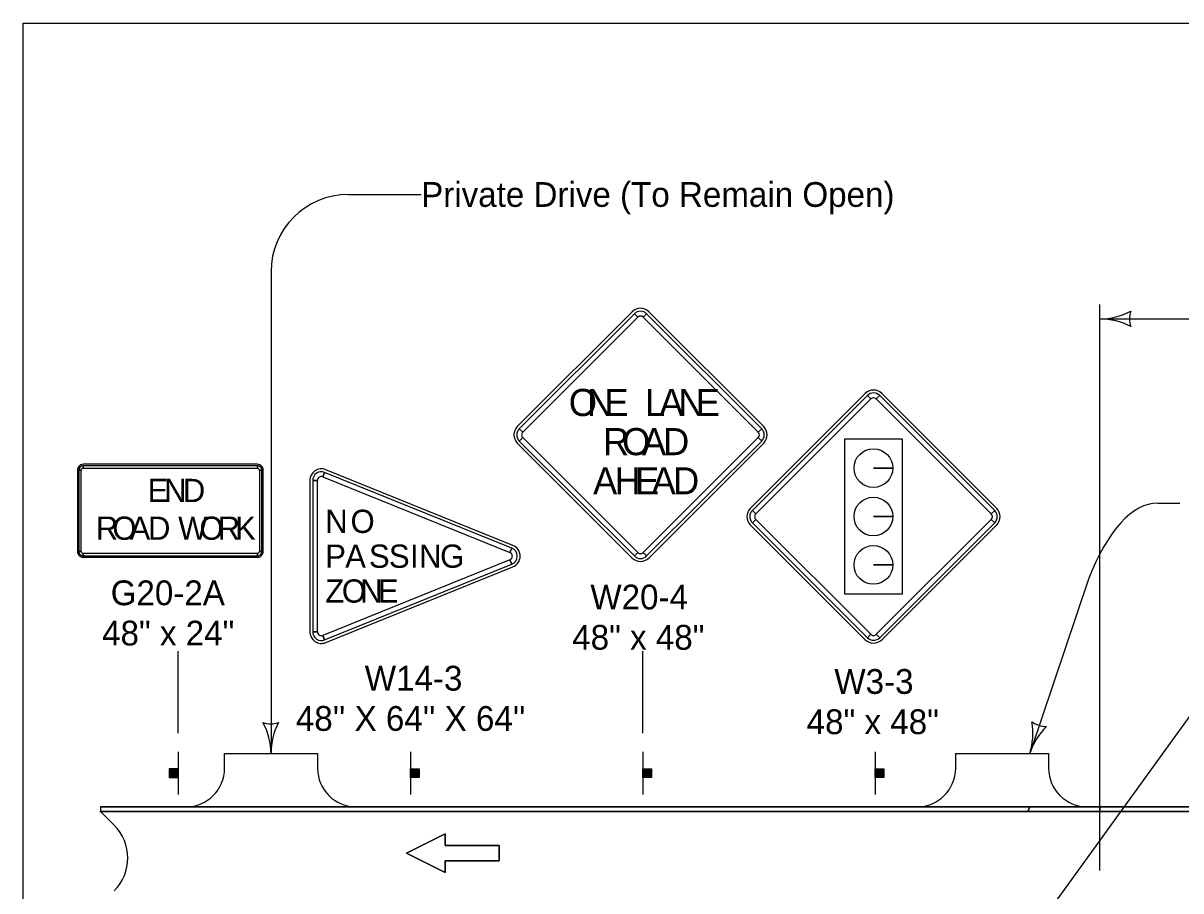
# Model space of a CAD drawing. Extents: x -2134934 to -2122394, y -2139046 to -2137036.
# Drawn here: x -2134934 to -2134187, y -2137596 to -2137036 of the extents above; entities that cross this region are included whole.
import ezdxf

# ---------------------------------------------------------------- set-up
doc = ezdxf.new("R2010")
doc.units = 0
for name, color, linetype in [('Barrier', 7, 'Continuous'), ('BridgeSuperStructureExisting', 7, 'Continuous'), ('Default', 7, 'Continuous'), ('DsnShtPlotIdentification', 7, 'Continuous'), ('DsnShtPlotShape', 7, 'Continuous')]:
    doc.layers.add(name, color=color, linetype=linetype)

msp = doc.modelspace()

# ---------------------------------------------------------------- linework, layer by layer
at = {"layer": 'Barrier'}
for p, q in [((-2134541.21, -2137222.31), (-2134615.45, -2137296.56)), ((-2134456.35, -2137296.56), (-2134530.6, -2137222.31)), ((-2134539.88, -2137223.64), (-2134537.67, -2137225.85)), ((-2134534.14, -2137225.85), (-2134531.93, -2137223.64)), ((-2134390.77, -2137275.12), (-2134465.02, -2137349.37)), ((-2134389.45, -2137276.45), (-2134387.24, -2137278.66)), ((-2134383.7, -2137278.66), (-2134381.49, -2137276.45)), ((-2134305.92, -2137349.37), (-2134380.17, -2137275.12)), ((-2134611.92, -2137300.09), (-2134614.13, -2137297.88)), ((-2134614.13, -2137305.84), (-2134611.92, -2137303.63)), ((-2134457.68, -2137297.88), (-2134459.89, -2137300.09)), ((-2134459.89, -2137303.63), (-2134457.68, -2137305.84)), ((-2134615.45, -2137307.16), (-2134541.21, -2137381.41)), ((-2134530.6, -2137381.41), (-2134456.35, -2137307.16)), ((-2134899.41, -2137324.64), (-2134899.41, -2137377.14)), ((-2134898.48, -2137324.64), (-2134896.91, -2137324.64)), ((-2134783.16, -2137320.89), (-2134895.66, -2137320.89)), ((-2134895.66, -2137323.39), (-2134895.66, -2137321.82)), ((-2134783.16, -2137321.82), (-2134783.16, -2137323.39)), ((-2134781.91, -2137324.64), (-2134780.35, -2137324.64)), ((-2134779.41, -2137377.14), (-2134779.41, -2137324.64)), ((-2134740.97, -2137329.01), (-2134739.8, -2137326.11)), ((-2134618.27, -2137373.25), (-2134739.1, -2137324.37)), ((-2134373.06, -2137323.34), (-2134385.56, -2137323.34)), ((-2134385.56, -2137323.34), (-2134373.06, -2137323.34)), ((-2134749.41, -2137331.32), (-2134749.41, -2137429.07)), ((-2134747.53, -2137331.32), (-2134744.41, -2137331.32)), ((-2134461.48, -2137352.9), (-2134463.69, -2137350.69)), ((-2134463.69, -2137358.65), (-2134461.48, -2137356.44)), ((-2134373.06, -2137354.59), (-2134385.56, -2137354.59)), ((-2134385.56, -2137354.59), (-2134373.06, -2137354.59)), ((-2134307.25, -2137350.69), (-2134309.45, -2137352.9)), ((-2134309.45, -2137356.44), (-2134307.25, -2137358.65)), ((-2134465.02, -2137359.98), (-2134390.77, -2137434.22)), ((-2134380.17, -2137434.22), (-2134305.92, -2137359.98)), ((-2134896.91, -2137377.14), (-2134898.48, -2137377.14)), ((-2134895.66, -2137379.95), (-2134895.66, -2137378.39)), ((-2134783.16, -2137378.39), (-2134783.16, -2137379.95)), ((-2134780.35, -2137377.14), (-2134781.91, -2137377.14)), ((-2134618.98, -2137374.98), (-2134620.15, -2137377.88)), ((-2134537.67, -2137377.87), (-2134539.88, -2137380.08)), ((-2134531.93, -2137380.08), (-2134534.14, -2137377.87)), ((-2134895.66, -2137380.89), (-2134783.16, -2137380.89)), ((-2134620.15, -2137382.52), (-2134618.98, -2137385.41)), ((-2134373.06, -2137385.84), (-2134385.56, -2137385.84)), ((-2134385.56, -2137385.84), (-2134373.06, -2137385.84)), ((-2134739.1, -2137436.03), (-2134618.27, -2137387.15)), ((-2134744.41, -2137429.07), (-2134747.53, -2137429.07)), ((-2134739.8, -2137434.29), (-2134740.97, -2137431.39)), ((-2134387.24, -2137430.69), (-2134389.45, -2137432.9)), ((-2134381.49, -2137432.9), (-2134383.7, -2137430.69))]:
    msp.add_line(p, q, dxfattribs=at)
for points in [[(-2134539.88, -2137223.64), (-2134614.13, -2137297.88), (-2134611.92, -2137300.09), (-2134537.67, -2137225.85), (-2134539.88, -2137223.64)], [(-2134457.68, -2137297.88), (-2134531.93, -2137223.64), (-2134534.14, -2137225.85), (-2134459.89, -2137300.09), (-2134457.68, -2137297.88)], [(-2134389.45, -2137276.45), (-2134463.69, -2137350.69), (-2134461.48, -2137352.9), (-2134387.24, -2137278.66), (-2134389.45, -2137276.45)], [(-2134307.25, -2137350.69), (-2134381.49, -2137276.45), (-2134383.7, -2137278.66), (-2134309.45, -2137352.9), (-2134307.25, -2137350.69)], [(-2134614.13, -2137305.84), (-2134539.88, -2137380.08), (-2134537.67, -2137377.87), (-2134611.92, -2137303.63), (-2134614.13, -2137305.84)], [(-2134531.93, -2137380.08), (-2134457.68, -2137305.84), (-2134459.89, -2137303.63), (-2134534.14, -2137377.87), (-2134531.93, -2137380.08)], [(-2134366.74, -2137304.73), (-2134404.2, -2137304.73), (-2134404.2, -2137404.62), (-2134366.74, -2137404.62), (-2134366.74, -2137304.73)], [(-2134898.48, -2137324.64), (-2134898.48, -2137377.14), (-2134896.91, -2137377.14), (-2134896.91, -2137324.64), (-2134898.48, -2137324.64)], [(-2134783.16, -2137321.82), (-2134895.66, -2137321.82), (-2134895.66, -2137323.39), (-2134783.16, -2137323.39), (-2134783.16, -2137321.82)], [(-2134780.35, -2137377.14), (-2134780.35, -2137324.64), (-2134781.91, -2137324.64), (-2134781.91, -2137377.14), (-2134780.35, -2137377.14)], [(-2134618.98, -2137374.98), (-2134739.8, -2137326.11), (-2134740.97, -2137329.01), (-2134620.15, -2137377.88), (-2134618.98, -2137374.98)], [(-2134747.53, -2137331.32), (-2134747.53, -2137429.07), (-2134744.41, -2137429.07), (-2134744.41, -2137331.32), (-2134747.53, -2137331.32)], [(-2134463.69, -2137358.65), (-2134389.45, -2137432.9), (-2134387.24, -2137430.69), (-2134461.48, -2137356.44), (-2134463.69, -2137358.65)], [(-2134381.49, -2137432.9), (-2134307.25, -2137358.65), (-2134309.45, -2137356.44), (-2134383.7, -2137430.69), (-2134381.49, -2137432.9)], [(-2134895.66, -2137379.95), (-2134783.16, -2137379.95), (-2134783.16, -2137378.39), (-2134895.66, -2137378.39), (-2134895.66, -2137379.95)], [(-2134739.8, -2137434.29), (-2134618.98, -2137385.41), (-2134620.15, -2137382.52), (-2134740.97, -2137431.39), (-2134739.8, -2137434.29)]]:
    msp.add_lwpolyline(points, close=True, dxfattribs=at)
for centre in [(-2134385.56, -2137323.34), (-2134385.56, -2137354.59), (-2134385.56, -2137385.84)]:
    msp.add_circle(centre, 12.5, dxfattribs=at)
for centre, radius, start, end in [((-2134535.9, -2137227.61), 7.5, 44.99999, 134.99974), ((-2134535.9, -2137227.61), 5.62, 44.99999, 134.99974), ((-2134535.9, -2137227.61), 2.5, 44.99999, 134.99974), ((-2134385.47, -2137280.43), 7.5, 44.99999, 134.99974), ((-2134385.47, -2137280.43), 5.62, 44.99999, 134.99974), ((-2134385.47, -2137280.43), 2.5, 44.99999, 134.99974), ((-2134610.15, -2137301.86), 7.5, 134.99974, 224.99995), ((-2134461.66, -2137301.86), 7.5, 315.00016, 44.9998), ((-2134610.15, -2137301.86), 5.62, 134.99974, 224.99995), ((-2134610.15, -2137301.86), 2.5, 134.99974, 224.99995), ((-2134461.66, -2137301.86), 2.5, 315.00016, 44.9998), ((-2134461.66, -2137301.86), 5.62, 315.00016, 44.9998), ((-2134895.66, -2137324.64), 3.75, 90.00021, 179.99985), ((-2134895.66, -2137324.64), 2.81, 90.00021, 179.99985), ((-2134895.66, -2137324.64), 1.25, 90.00021, 179.99985), ((-2134783.16, -2137324.64), 3.75, 0, 90.00021), ((-2134783.16, -2137324.64), 2.81, 0, 90.00021), ((-2134783.16, -2137324.64), 1.25, 0, 90.00021), ((-2134741.91, -2137331.32), 7.5, 67.97571, 179.99985), ((-2134741.91, -2137331.32), 5.62, 67.97571, 179.99985), ((-2134741.91, -2137331.32), 2.5, 67.97571, 179.99985), ((-2134459.72, -2137354.67), 7.5, 134.99974, 224.99995), ((-2134311.22, -2137354.67), 7.5, 315.00016, 44.9998), ((-2134459.72, -2137354.67), 5.62, 134.99974, 224.99995), ((-2134459.72, -2137354.67), 2.5, 134.99974, 224.99995), ((-2134311.22, -2137354.67), 2.5, 315.00016, 44.9998), ((-2134311.22, -2137354.67), 5.62, 315.00016, 44.9998), ((-2134895.66, -2137377.14), 3.75, 179.99985, 270.00006), ((-2134895.66, -2137377.14), 2.81, 179.99985, 270.00006), ((-2134895.66, -2137377.14), 1.25, 179.99985, 270.00006), ((-2134783.16, -2137377.14), 3.75, 270.00006, 0.00027), ((-2134783.16, -2137377.14), 2.81, 270.00006, 0.00027), ((-2134783.16, -2137377.14), 1.25, 270.00006, 0.00027), ((-2134621.09, -2137380.2), 2.5, 292.02456, 67.97541), ((-2134621.09, -2137380.2), 5.62, 292.02456, 67.97541), ((-2134621.09, -2137380.2), 7.5, 292.02456, 67.97598), ((-2134535.9, -2137376.11), 2.5, 224.99995, 315.00016), ((-2134535.9, -2137376.11), 7.5, 224.99995, 315.00016), ((-2134535.9, -2137376.11), 5.62, 224.99995, 315.00016), ((-2134741.91, -2137429.07), 7.5, 179.99985, 292.02456), ((-2134741.91, -2137429.07), 5.62, 179.99985, 292.02456), ((-2134741.91, -2137429.07), 2.5, 179.99985, 292.02456), ((-2134385.47, -2137428.92), 2.5, 224.99995, 315.00016), ((-2134385.47, -2137428.92), 7.5, 224.99995, 315.00016), ((-2134385.47, -2137428.92), 5.62, 224.99995, 315.00016)]:
    msp.add_arc(centre, radius, start, end, dxfattribs=at)
at = {"layer": 'BridgeSuperStructureExisting'}
for p, q in [((-2134724.38, -2137146.61), (-2134677.51, -2137146.61)), ((-2134774.38, -2137196.61), (-2134774.38, -2137507.67)), ((-2134239.44, -2137583.23), (-2134239.44, -2137217.69)), ((-2134239.44, -2137226.98), (-2133580.02, -2137226.98)), ((-2134202.01, -2137345.99), (-2134187.79, -2137345.99)), ((-2134246.74, -2137395.12), (-2134284.66, -2137507.67)), ((-2134834.44, -2137494.5), (-2134834.44, -2137441.62)), ((-2134534.44, -2137494.5), (-2134534.44, -2137441.62)), ((-2134351.45, -2137718.98), (-2134176.64, -2137477.16)), ((-2134834.44, -2137506.66), (-2134834.44, -2137534.16)), ((-2134684.44, -2137506.66), (-2134684.44, -2137534.16)), ((-2134534.44, -2137506.66), (-2134534.44, -2137534.16)), ((-2134384.44, -2137506.66), (-2134384.44, -2137534.16)), ((-2134839.77, -2137517.52), (-2134839.77, -2137523.11)), ((-2134839.45, -2137523.11), (-2134839.45, -2137517.52)), ((-2134839.22, -2137517.52), (-2134839.22, -2137523.11)), ((-2134838.9, -2137523.11), (-2134838.9, -2137517.52)), ((-2134838.68, -2137517.52), (-2134838.7, -2137523.11)), ((-2134838.27, -2137523.11), (-2134838.25, -2137517.52)), ((-2134838.04, -2137517.52), (-2134838.04, -2137523.11)), ((-2134837.61, -2137523.11), (-2134837.61, -2137517.52)), ((-2134837.24, -2137517.52), (-2134837.24, -2137523.11)), ((-2134836.92, -2137523.11), (-2134836.9, -2137517.52)), ((-2134836.69, -2137517.52), (-2134836.69, -2137523.11)), ((-2134836.43, -2137523.11), (-2134836.43, -2137517.52)), ((-2134836.09, -2137517.52), (-2134836.09, -2137523.11)), ((-2134835.89, -2137523.11), (-2134835.89, -2137517.52)), ((-2134835.66, -2137517.52), (-2134835.66, -2137523.11)), ((-2134835.4, -2137523.11), (-2134835.4, -2137517.52)), ((-2134835.14, -2137517.52), (-2134835.14, -2137523.11)), ((-2134834.85, -2137523.11), (-2134834.85, -2137517.52)), ((-2134684.03, -2137523.11), (-2134684.03, -2137517.52)), ((-2134683.75, -2137517.52), (-2134683.75, -2137523.11)), ((-2134683.48, -2137523.11), (-2134683.48, -2137517.52)), ((-2134683.22, -2137517.52), (-2134683.22, -2137523.11)), ((-2134683, -2137523.11), (-2134683, -2137517.52)), ((-2134682.79, -2137517.52), (-2134682.79, -2137523.11)), ((-2134682.45, -2137523.11), (-2134682.45, -2137517.52)), ((-2134682.19, -2137517.52), (-2134682.19, -2137523.11)), ((-2134681.97, -2137523.11), (-2134681.98, -2137517.52)), ((-2134681.65, -2137517.52), (-2134681.65, -2137523.11)), ((-2134681.27, -2137523.11), (-2134681.27, -2137517.52)), ((-2134680.84, -2137517.52), (-2134680.84, -2137523.11)), ((-2134680.62, -2137523.11), (-2134680.63, -2137517.52)), ((-2134680.2, -2137517.52), (-2134680.18, -2137523.11)), ((-2134679.98, -2137523.11), (-2134679.98, -2137517.52)), ((-2134679.66, -2137517.52), (-2134679.66, -2137523.11)), ((-2134679.43, -2137523.11), (-2134679.43, -2137517.52)), ((-2134679.12, -2137517.52), (-2134679.12, -2137523.11)), ((-2134534.03, -2137523.11), (-2134534.03, -2137517.52)), ((-2134533.75, -2137517.52), (-2134533.75, -2137523.11)), ((-2134533.48, -2137523.11), (-2134533.48, -2137517.52)), ((-2134533.22, -2137517.52), (-2134533.22, -2137523.11)), ((-2134533, -2137523.11), (-2134533, -2137517.52)), ((-2134532.79, -2137517.52), (-2134532.79, -2137523.11)), ((-2134532.45, -2137523.11), (-2134532.45, -2137517.52)), ((-2134532.19, -2137517.52), (-2134532.19, -2137523.11)), ((-2134531.97, -2137523.11), (-2134531.98, -2137517.52)), ((-2134531.65, -2137517.52), (-2134531.65, -2137523.11)), ((-2134531.27, -2137523.11), (-2134531.27, -2137517.52)), ((-2134530.84, -2137517.52), (-2134530.84, -2137523.11)), ((-2134530.62, -2137523.11), (-2134530.63, -2137517.52)), ((-2134530.2, -2137517.52), (-2134530.18, -2137523.11)), ((-2134529.98, -2137523.11), (-2134529.98, -2137517.52)), ((-2134529.66, -2137517.52), (-2134529.66, -2137523.11)), ((-2134529.43, -2137523.11), (-2134529.43, -2137517.52)), ((-2134529.12, -2137517.52), (-2134529.12, -2137523.11)), ((-2134384.03, -2137523.11), (-2134384.03, -2137517.52)), ((-2134383.75, -2137517.52), (-2134383.75, -2137523.11)), ((-2134383.48, -2137523.11), (-2134383.48, -2137517.52)), ((-2134383.22, -2137517.52), (-2134383.22, -2137523.11)), ((-2134383, -2137523.11), (-2134383, -2137517.52)), ((-2134382.79, -2137517.52), (-2134382.79, -2137523.11)), ((-2134382.45, -2137523.11), (-2134382.45, -2137517.52)), ((-2134382.19, -2137517.52), (-2134382.19, -2137523.11)), ((-2134381.97, -2137523.11), (-2134381.98, -2137517.52)), ((-2134381.65, -2137517.52), (-2134381.65, -2137523.11)), ((-2134381.27, -2137523.11), (-2134381.27, -2137517.52)), ((-2134380.84, -2137517.52), (-2134380.84, -2137523.11)), ((-2134380.62, -2137523.11), (-2134380.63, -2137517.52)), ((-2134380.2, -2137517.52), (-2134380.18, -2137523.11)), ((-2134379.98, -2137523.11), (-2134379.98, -2137517.52)), ((-2134379.66, -2137517.52), (-2134379.66, -2137523.11)), ((-2134379.43, -2137523.11), (-2134379.43, -2137517.52)), ((-2134379.12, -2137517.52), (-2134379.12, -2137523.11)), ((-2134719.38, -2137542.16), (-2134829.38, -2137542.16)), ((-2134247.44, -2137542.16), (-2134357.44, -2137542.16)), ((-2134875.66, -2137553.94), (-2134884.44, -2137545.16)), ((-2133574.44, -2137545.16), (-2134884.44, -2137545.16)), ((-2134884.44, -2137545.16), (-2134875.65, -2137553.95))]:
    msp.add_line(p, q, dxfattribs=at)
for points in [[(-2134804.38, -2137517.16), (-2134804.38, -2137507.67), (-2134744.38, -2137507.67), (-2134744.38, -2137517.16)], [(-2134332.44, -2137517.16), (-2134332.44, -2137507.67), (-2134272.44, -2137507.67), (-2134272.44, -2137517.16)], [(-2134662.04, -2137577), (-2134662.04, -2137584.5), (-2134687.04, -2137572), (-2134662.04, -2137559.5), (-2134662.04, -2137567), (-2134627.04, -2137567), (-2134627.04, -2137577), (-2134662.04, -2137577)]]:
    msp.add_lwpolyline(points, dxfattribs=at)
for points in [[(-2134834.54, -2137523.11), (-2134834.54, -2137517.48), (-2134840.16, -2137517.48), (-2134840.16, -2137523.11)], [(-2134684.35, -2137523.11), (-2134684.35, -2137517.48), (-2134678.72, -2137517.48), (-2134678.72, -2137523.11)], [(-2134534.35, -2137523.11), (-2134534.35, -2137517.48), (-2134528.72, -2137517.48), (-2134528.72, -2137523.11)], [(-2134384.35, -2137523.11), (-2134384.35, -2137517.48), (-2134378.72, -2137517.48), (-2134378.72, -2137523.11)], [(-2134627.04, -2137577), (-2134627.04, -2137567), (-2134662.04, -2137567), (-2134662.04, -2137559.5), (-2134687.04, -2137572), (-2134662.04, -2137584.5), (-2134662.04, -2137577)]]:
    msp.add_lwpolyline(points, close=True, dxfattribs=at)
for centre, radius, start, end in [((-2134724.38, -2137196.61), 50, 90, 180), ((-2134829.38, -2137517.16), 25, 270, 0), ((-2134719.38, -2137517.16), 25, 180, 270), ((-2134357.44, -2137517.16), 25, 270, 360), ((-2134247.44, -2137517.16), 25, 180, 270), ((-2134896.87, -2137575.16), 30, 315, 45), ((-2134896.87, -2137575.16), 30, 315, 45)]:
    msp.add_arc(centre, radius, start, end, dxfattribs=at)
msp.add_ellipse((-2134202.01, -2137558.92), major_axis=(0, 212.93), ratio=0.328743, start_param=0, end_param=0.693162, dxfattribs=at)
at = {"layer": 'Default'}
msp.add_lwpolyline([(-2134934.44, -2137035.95), (-2131799.45, -2137035.95), (-2131799.45, -2139045.94), (-2134934.44, -2139045.94)], close=True, dxfattribs=at)
at = {"layer": 'DsnShtPlotIdentification'}
for p, q in [((-2134884.44, -2137542.16), (-2134884.44, -2137545.16)), ((-2134884.44, -2137542.16), (-2134884.44, -2137545.16)), ((-2134284.66, -2137542.16), (-2134884.44, -2137542.16)), ((-2134284.66, -2137542.16), (-2134285.86, -2137545.16)), ((-2134285.86, -2137545.16), (-2134284.66, -2137542.16)), ((-2134239.44, -2137542.16), (-2134284.66, -2137542.16)), ((-2133766.47, -2137542.16), (-2134239.44, -2137542.16)), ((-2134239.44, -2137542.16), (-2134239.44, -2137545.16)), ((-2134239.44, -2137545.16), (-2134239.44, -2137542.16)), ((-2134884.44, -2137545.16), (-2134285.86, -2137545.16)), ((-2134285.86, -2137545.16), (-2134239.44, -2137545.16)), ((-2134239.44, -2137545.16), (-2133764.3, -2137545.16))]:
    msp.add_line(p, q, dxfattribs=at)
for points in [[(-2134884.44, -2137542.16), (-2133574.44, -2137542.16)], [(-2134884.86, -2137545.16), (-2133574.86, -2137545.16)], [(-2134884.44, -2137545.16), (-2133574.44, -2137545.16)]]:
    msp.add_lwpolyline(points, dxfattribs=at)
at = {"layer": 'DsnShtPlotShape'}
for centre, radius, start, end in [((-2134239.44, -2137184.48), 42.5, 270, 298.07249), ((-2134203.81, -2137226.98), 16.42, 162.26665, 197.73335), ((-2134239.44, -2137269.48), 42.5, 61.92751, 90), ((-2134774.82, -2137472.04), 16.42, 252.97281, 288.43951), ((-2134816.87, -2137508.19), 42.5, 0.70616, 28.77865), ((-2134731.88, -2137507.15), 42.5, 152.63367, 180.70616), ((-2134325.1, -2137494.6), 42.5, 342.08492, 10.15741), ((-2134244.23, -2137520.74), 42.5, 134.01243, 162.08492), ((-2134273.7, -2137473.76), 16.42, 234.35157, 269.81827)]:
    msp.add_arc(centre, radius, start, end, dxfattribs=at)

# ---------------------------------------------------------------- texts
at = {"layer": 'Barrier'}
for s, height, p in [('O', 17.5, (-2134582.19, -2137289.67)), ('N', 17.5, (-2134570.41, -2137289.67)), ('E', 17.5, (-2134559.19, -2137289.67)), ('L', 17.5, (-2134532.94, -2137289.67)), ('A', 17.5, (-2134523.74, -2137289.67)), ('N', 17.5, (-2134511.47, -2137289.67)), ('E', 17.5, (-2134500.24, -2137289.67)), ('O', 17.5, (-2134547.79, -2137314.98)), ('R', 17.5, (-2134560.08, -2137314.98)), ('A', 17.5, (-2134534.95, -2137314.98)), ('D', 17.5, (-2134521.3, -2137314.98)), ('A', 17.5, (-2134566.52, -2137340.3)), ('H', 17.5, (-2134552.65, -2137340.3)), ('E', 17.5, (-2134539.44, -2137340.3)), ('A', 17.5, (-2134528.72, -2137340.3)), ('D', 17.5, (-2134514.86, -2137340.3)), ('E', 15, (-2134854.09, -2137345.26)), ('N', 15, (-2134843.47, -2137345.26)), ('D', 15, (-2134831.38, -2137345.26)), ('R', 15, (-2134887.55, -2137369.64)), ('O', 15, (-2134876.87, -2137369.64)), ('A', 15, (-2134865.71, -2137369.64)), ('D', 15, (-2134853.85, -2137369.64)), ('W', 15, (-2134834.4, -2137369.64)), ('O', 15, (-2134820.67, -2137369.64)), ('R', 15, (-2134808.9, -2137369.64)), ('K', 15, (-2134797.6, -2137369.64)), ('N', 15, (-2134739.44, -2137365.2)), ('O', 15, (-2134723.1, -2137365.2)), ('P', 15, (-2134739.44, -2137387.7)), ('A', 15, (-2134726.55, -2137387.7)), ('S', 15, (-2134711.2, -2137387.7)), ('S', 15, (-2134698.31, -2137387.7)), ('I', 15, (-2134684.71, -2137387.7)), ('N', 15, (-2134678.85, -2137387.7)), ('G', 15, (-2134665.26, -2137387.7)), ('G20-2A', 16, (-2134877.94, -2137411.89)), ('Z', 15, (-2134739.44, -2137410.2)), ('O', 15, (-2134728.7, -2137410.2)), ('N', 15, (-2134716.87, -2137410.2)), ('E', 15, (-2134705.51, -2137410.2)), ('W20-4', 16, (-2134568.27, -2137414.61)), ('48" x 24"', 16, (-2134883.48, -2137437.89)), ('48" x 48"', 16, (-2134579.97, -2137440.61)), ('W14-3', 16, (-2134713.9, -2137467.03)), ('W3-3', 16, (-2134410.76, -2137469.14)), ("48'' X 64'' X 64''", 16, (-2134758.39, -2137493.03)), ('48" x 48"', 16, (-2134428.64, -2137495.14))]:
    msp.add_text(s, height=height, dxfattribs=at).set_placement(p)
at = {"layer": 'BridgeSuperStructureExisting'}
msp.add_text('Private Drive (To Remain Open)', height=16, dxfattribs=at).set_placement((-2134677.51, -2137154.61))

doc.saveas('drawing.dxf')
